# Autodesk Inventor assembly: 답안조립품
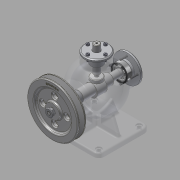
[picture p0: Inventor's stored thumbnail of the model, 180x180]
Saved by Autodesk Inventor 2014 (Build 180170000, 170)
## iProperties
Created: 2015-10
Part Number: 답안조립품
Document SubType Name: Assembly
Designer: youjin09
Author: youjin09
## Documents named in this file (19)
- C:\Users\youjin09\Desktop\451010V1004\답안조립품.iam
- C:\Users\youjin09\Desktop\451010V1004\본체.ipt
- C:\Users\youjin09\Desktop\451010V1004\앞커버.ipt
- C:\Users\youjin09\Desktop\451010V1004\뒤커버.ipt
- C:\Users\youjin09\Desktop\451010V1004\상부커버.ipt
- C:\Users\youjin09\Desktop\451010V1004\볼트 M 4 x 12.ipt
- C:\Users\youjin09\Desktop\451010V1004\볼트 M4 x 16.ipt
- C:\Users\youjin09\Desktop\451010V1004\베어링- 6202.ipt
- KS B 2023 - 6202 - 15 x 35 x 11 - 7.8.ipt
- C:\Users\youjin09\Desktop\451010V1004\멈춤링- 15 x 1.ipt
- C:\Users\youjin09\Desktop\451010V1004\멈춤링- 35x1.6.ipt
- KS B 1336 - 35x1.6.ipt
- C:\Users\youjin09\Desktop\451010V1004\부시.ipt
- C:\Users\youjin09\Desktop\451010V1004\오일실 15 30 7.ipt
- C:\Users\youjin09\Desktop\451010V1004\편심축.ipt
- C:\Users\youjin09\Desktop\451010V1004\키 4 x 4 x 12.ipt
- C:\Users\youjin09\Desktop\451010V1004\너트 M8.ipt
- C:\Users\youjin09\Desktop\451010V1004\V-벨트풀리.ipt
- C:\Users\youjin09\Desktop\451010V1004\슬라이드.ipt
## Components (16 placed, 5 different names)
1. KS B 2023 - 6202 - 15 x 35 x 11 - 7.8:1 — Mate:12, Mate:13, Mate:18, Mate:19
2. KS B 2023 - 6202 - 15 x 35 x 11 - 7.8:2 — Mate:10, Mate:11, Mate:14, Mate:15, Mate:16, Mate:17
3. KS B 1336 - 35x1.6:1 — Mate:16, Mate:17
4. V-벨트풀리:1 — Mate:29, Mate:30, Mate:31
5. KS B 1021 - 에 따름 ISO 1207 - 미터 A  M 4 x 12:1 — Insert:1
6. KS B 1021 - 에 따름 ISO 1207 - 미터 A  M 4 x 12:2
7. KS B 1021 - 에 따름 ISO 1207 - 미터 A  M 4 x 12:3
8. KS B 1021 - 에 따름 ISO 1207 - 미터 A  M 4 x 12:4
9. ISO 4762 M4 x 16:1 — Insert:2
10. ISO 4762 M4 x 16:3
11. ISO 4762 M4 x 16:4
12. ISO 4762 M4 x 16:5
13. ISO 4762 M4 x 16:2 — Insert:3
14. ISO 4762 M4 x 16:6
15. ISO 4762 M4 x 16:7
16. ISO 4762 M4 x 16:8
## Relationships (16: Mate 13, Insert 3)
- Insert:1: KS B 1021 - 에 따름 ISO 1207 - 미터 A  M 4 x 12:1
- Insert:2: ISO 4762 M4 x 16:1
- Insert:3: ISO 4762 M4 x 16:2
- Mate:10: KS B 2023 - 6202 - 15 x 35 x 11 - 7.8:2
- Mate:11: KS B 2023 - 6202 - 15 x 35 x 11 - 7.8:2
- Mate:12: KS B 2023 - 6202 - 15 x 35 x 11 - 7.8:1
- Mate:13: KS B 2023 - 6202 - 15 x 35 x 11 - 7.8:1
- Mate:14: KS B 2023 - 6202 - 15 x 35 x 11 - 7.8:2
- Mate:15: KS B 2023 - 6202 - 15 x 35 x 11 - 7.8:2
- Mate:16: KS B 2023 - 6202 - 15 x 35 x 11 - 7.8:2 ↔ KS B 1336 - 35x1.6:1
- Mate:17: KS B 2023 - 6202 - 15 x 35 x 11 - 7.8:2 ↔ KS B 1336 - 35x1.6:1
- Mate:18: KS B 2023 - 6202 - 15 x 35 x 11 - 7.8:1
- Mate:19: KS B 2023 - 6202 - 15 x 35 x 11 - 7.8:1
- Mate:29: V-벨트풀리:1
- Mate:30: V-벨트풀리:1
- Mate:31: V-벨트풀리:1
